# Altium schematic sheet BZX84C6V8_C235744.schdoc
size 127 x 101 mm
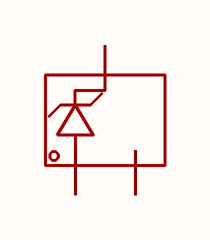
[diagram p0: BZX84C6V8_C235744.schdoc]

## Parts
D?  bzx84c6v8  [SOT-23-3_L2.9-W1.6-P1.90-LS2.8-BR]  (value not drawn)

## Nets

Not connected (* = marked no-connect by the designer): D? 1 2 3

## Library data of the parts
D? = bzx84c6v8: 二极管配置:1个独立式;稳压值(标称值):6.8V;稳压值(范围):6.4V~7.2V;耗散功率(Pd):300mW;; Manufacturer: CJ(江苏长电/长晶); Symbol: BZX84C6V8_C235744; AddInBom: yes; ModelId: 89cb27a44ab2466697082bb9fd73a7d0; ModelName: SOT-23-3L_L2.9-W1.6-H1.1-LS2.8-P0.95; ModelTransform: 114.173,110.236,0,90,0,0,0,0,0; Diode Configuration: 1个独立式; Zener Voltage(Nom): 6.8V; Reverse Leakage Current (Ir): 2uA@4V; Pd - Power Dissipation: 300mW; Impedance(Zzt): 15Ω; Impedance(Zzk): 80Ω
